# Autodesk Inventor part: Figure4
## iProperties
Shininess: 77.0
Length Units: 11269
Angle Units: 11279
Time Units: 11290
Mass Units: 11283
Length Display Precision: 3
Angle Display Precision: 2
Created: 2001-12
Part Number: Figure4
Document SubType Name: Modeling
Designer: CADSoft
Density: 0.0
Volumn: 0.0
Area: 0.0
PropertySet Name: Model Information
Control State: 0
Master: False
Checked Out: False
Author: CADSoft
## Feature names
1. Loft1
